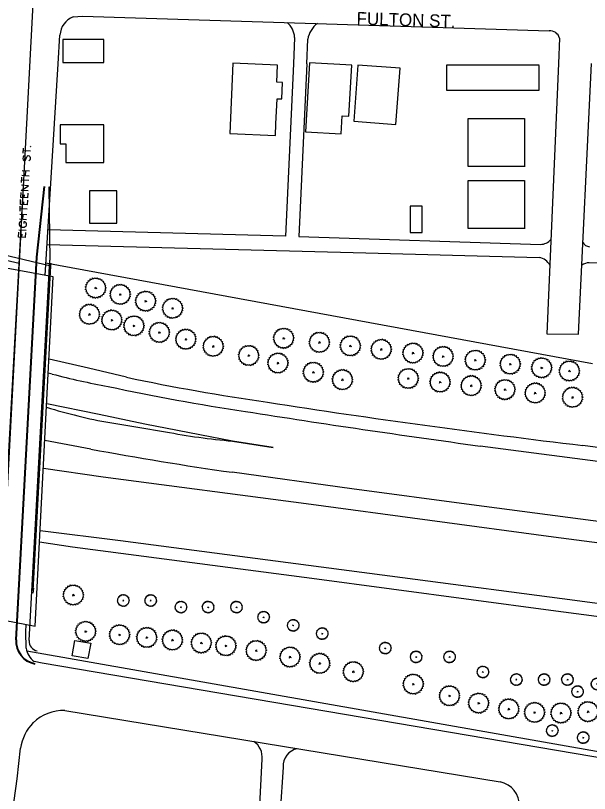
# Model space of a CAD drawing. Extents: x -9648 to 41057, y -12373 to 40276.
# Drawn here: x 11005 to 11458, y -5031 to -4417 of the extents above; entities that cross this region are included whole.
import ezdxf

# ---------------------------------------------------------------- set-up
doc = ezdxf.new("R2010")
doc.units = 0
for name, color, linetype in [('Default', 7, 'Continuous'), ('GE_P_CL_50', 7, 'Continuous'), ('PM_X_Channelizing_Line', 7, 'Continuous'), ('PM_X_Dotted_Line', 7, 'Continuous'), ('PM_X_Stop_Line', 7, 'Continuous'), ('PV_P_Shoulder', 7, 'Continuous'), ('SC_Scratch1', 7, 'Continuous'), ('SH_Data', 7, 'Continuous'), ('TX_P_100', 7, 'Continuous')]:
    doc.layers.add(name, color=color, linetype=linetype)

# ---------------------------------------------------------------- blocks, each defined once
blk = doc.blocks.new('15_PIN')
at = {"layer": 'Default'}
for p, q in [((-2.8, 0), (2.8, 0)), ((0, 2.8), (0, -2.8))]:
    blk.add_line(p, q, dxfattribs=at)
for centre, start, end in [((-16.7, 19.8), 235.99, 24.01), ((-11.6, 23.2), 222.6567, 10.6766), ((-6, 25.2), 209.3234, 357.3433), ((0, 25.9), 195.99, 344.01), ((6, 25.2), 182.6567, 330.6766), ((11.6, 23.2), 169.3234, 317.3433), ((16.7, 19.8), 155.99, 304.01), ((-25.5, 4.5), 275.99, 64.01), ((-25.9, -1.5), 289.3234, 77.3433), ((-23.8, 10.3), 262.6567, 50.6766), ((-20.8, 15.5), 249.3234, 37.3433), ((20.8, 15.5), 142.6567, 290.6766), ((23.8, 10.3), 129.3234, 277.3433), ((25.5, 4.5), 115.99, 264.01), ((25.9, -1.5), 102.6567, 250.6766), ((-24.8, -7.4), 302.6567, 90.6766), ((-22.4, -13), 315.99, 104.01), ((-18.8, -17.8), 329.3234, 117.3433), ((-14.2, -21.6), 342.6567, 130.6766), ((14.2, -21.6), 49.3234, 197.3433), ((18.8, -17.8), 62.6567, 210.6767), ((22.4, -13), 75.99, 224.01), ((24.8, -7.4), 89.3234, 237.3433), ((-8.9, -24.3), 355.99, 144.01), ((-3, -25.7), 9.3234, 157.3433), ((3, -25.7), 22.6567, 170.6766), ((8.9, -24.3), 35.99, 184.01)]:
    blk.add_arc(centre, 3.05, start, end, dxfattribs=at)

msp = doc.modelspace()

# ---------------------------------------------------------------- linework, layer by layer
at = {"layer": 'GE_P_CL_50'}
for p, q in [((11022.27, -4607.98), (11028.39, -4552.14)), ((11031.46, -4552.28), (11032.16, -4610.35)), ((11005.84, -4909.67), (11022.27, -4607.98)), ((11015.82, -4910.22), (11032.16, -4610.35))]:
    msp.add_line(p, q, dxfattribs=at)
for radius in [18, 8]:
    msp.add_arc((11023.81, -4910.65), radius, 176.88179, 259.41889, dxfattribs=at)
at = {"layer": 'PM_X_Channelizing_Line'}
for p, q in [((11021.77, -4607.98), (11027.88, -4552.16)), ((11005.34, -4909.65), (11021.78, -4607.9))]:
    msp.add_line(p, q, dxfattribs=at)
msp.add_arc((11023.81, -4910.65), 18.5, 176.88179, 259.41889, dxfattribs=at)
at = {"layer": 'PM_X_Dotted_Line'}
msp.add_line((10993.12, -4885.67), (11011.35, -4551.18), dxfattribs=at)
at = {"layer": 'PM_X_Stop_Line'}
for p in [(10981.18, -4602.61), (11018.97, -4870.86)]:
    msp.add_line(p, (11032.93, -4614.63), dxfattribs=at)
msp.add_arc((9361.23, -8468.95), 3904.03, 82.5, 82.5, dxfattribs=at)
at = {"layer": 'PV_P_Shoulder'}
msp.add_line((10980.21, -4606.15), (11008, -4612.61), dxfattribs=at)
at = {"layer": 'SC_Scratch1'}
for p, q in [((10990.47, -4947.21), (11071.82, -3407.25)), ((10949.85, -5716.14), (11031.09, -4178.28)), ((11011.47, -4521.79), (11011.47, -4521.79)), ((11016.7, -4520.6), (11016.7, -4520.6)), ((11016.91, -4520.86), (11016.91, -4520.86)), ((11016.93, -4520.37), (11016.93, -4520.37)), ((11017.14, -4520.63), (11017.14, -4520.63)), ((11011.25, -4525.85), (11011.25, -4525.85)), ((11011.36, -4523.76), (11011.36, -4523.76)), ((11011.93, -4527.62), (11011.93, -4527.62)), ((11014.6, -4528.01), (11014.6, -4528.01)), ((11015.18, -4527.8), (11015.18, -4527.8)), ((11015.96, -4527.84), (11015.96, -4527.84)), ((11016.95, -4524.07), (11016.95, -4524.07)), ((11011, -4530.16), (11011, -4530.16)), ((11011.07, -4529.05), (11011.07, -4529.05)), ((11011.18, -4531.03), (11011.18, -4531.03)), ((11011.34, -4528.2), (11011.34, -4528.2)), ((11011.71, -4531.68), (11011.71, -4531.68)), ((11012.27, -4531.71), (11012.27, -4531.71)), ((11012.84, -4531.49), (11012.84, -4531.49)), ((11013.08, -4531.26), (11013.08, -4531.26)), ((11013.34, -4530.66), (11013.34, -4530.66)), ((11013.99, -4528.84), (11013.99, -4528.84)), ((11014.25, -4528.37), (11014.25, -4528.37)), ((11015.73, -4531.9), (11015.73, -4531.9)), ((11016.33, -4531.32), (11016.33, -4531.32)), ((11016.48, -4528.49), (11016.48, -4528.49)), ((11016.6, -4530.47), (11016.6, -4530.47)), ((11016.66, -4529.36), (11016.66, -4529.36)), ((11010.49, -4539.51), (11010.49, -4539.51)), ((11013.17, -4539.66), (11013.17, -4539.66)), ((11016.08, -4539.82), (11016.08, -4539.82)), ((11010.2, -4544.8), (11010.2, -4544.8)), ((11010.26, -4543.57), (11010.26, -4543.57)), ((11012.95, -4543.72), (11012.95, -4543.72)), ((11015.85, -4543.88), (11015.85, -4543.88)), ((11009.84, -4551.19), (11009.84, -4551.19)), ((11009.97, -4548.86), (11009.97, -4548.86)), ((11010.08, -4546.77), (11010.08, -4546.77)), ((11015.43, -4551.51), (11015.43, -4551.51)), ((11015.68, -4547.07), (11015.68, -4547.07)), ((11009.52, -4556.98), (11009.52, -4556.98)), ((11009.61, -4555.25), (11009.61, -4555.25)), ((11012.12, -4558.6), (11012.12, -4558.6)), ((11015.11, -4557.28), (11015.11, -4557.28)), ((11015.2, -4555.56), (11015.2, -4555.56)), ((11009.21, -4562.51), (11009.21, -4562.51)), ((11009.31, -4560.79), (11009.31, -4560.79)), ((11011.81, -4564.14), (11011.81, -4564.14)), ((11011.99, -4560.94), (11011.99, -4560.94)), ((11014.8, -4562.82), (11014.8, -4562.82)), ((11014.9, -4561.1), (11014.9, -4561.1)), ((11014.9, -4561.1), (11014.9, -4561.1)), ((11008.82, -4569.52), (11008.82, -4569.52)), ((11008.93, -4567.55), (11008.93, -4567.55)), ((11009, -4566.33), (11009, -4566.33)), ((11011.68, -4566.47), (11011.68, -4566.47)), ((11014.41, -4569.83), (11014.41, -4569.83)), ((11014.59, -4566.63), (11014.59, -4566.63)), ((11014.59, -4566.63), (11014.59, -4566.63)), ((11008.58, -4573.95), (11008.58, -4573.95)), ((11008.71, -4571.61), (11008.71, -4571.61)), ((11011.26, -4574.1), (11011.26, -4574.1)), ((11014.17, -4574.26), (11014.17, -4574.26)), ((11008.1, -4582.44), (11008.1, -4582.44)), ((11008.17, -4581.21), (11008.17, -4581.21)), ((11008.3, -4582.94), (11008.3, -4582.94)), ((11008.35, -4578.01), (11008.35, -4578.01)), ((11008.43, -4580.61), (11008.43, -4580.61)), ((11009.02, -4580.14), (11009.02, -4580.14)), ((11009.59, -4579.81), (11009.59, -4579.81)), ((11011.03, -4578.16), (11011.03, -4578.16)), ((11011.64, -4581.4), (11011.64, -4581.4)), ((11011.72, -4579.93), (11011.72, -4579.93)), ((11012.5, -4579.97), (11012.5, -4579.97)), ((11013.04, -4580.37), (11013.04, -4580.37)), ((11013.45, -4583.23), (11013.45, -4583.23)), ((11013.58, -4580.89), (11013.58, -4580.89)), ((11013.7, -4582.75), (11013.7, -4582.75)), ((11013.76, -4581.52), (11013.76, -4581.52)), ((11013.94, -4578.32), (11013.94, -4578.32)), ((11007.78, -4588.22), (11007.78, -4588.22)), ((11007.88, -4586.5), (11007.88, -4586.5)), ((11008.82, -4583.59), (11008.82, -4583.59)), ((11009.36, -4583.99), (11009.36, -4583.99)), ((11010.13, -4584.28), (11010.13, -4584.28)), ((11011.47, -4584.35), (11011.47, -4584.35)), ((11012.27, -4584.15), (11012.27, -4584.15)), ((11012.85, -4583.81), (11012.85, -4583.81)), ((11013.37, -4588.53), (11013.37, -4588.53)), ((11013.47, -4586.81), (11013.47, -4586.81)), ((11007.57, -4592.03), (11007.57, -4592.03)), ((11010.25, -4592.18), (11010.25, -4592.18)), ((11010.38, -4589.85), (11010.38, -4589.85)), ((11013.16, -4592.34), (11013.16, -4592.34))]:
    msp.add_line(p, q, dxfattribs=at)
for points in [[(11011.25, -4525.85), (11011.47, -4521.79)], [(11011.25, -4525.85), (11011.47, -4521.79)], [(11016.7, -4520.6), (11016.91, -4520.86), (11017.14, -4520.63), (11016.93, -4520.37)], [(11016.7, -4520.6), (11016.91, -4520.86), (11017.14, -4520.63), (11016.93, -4520.37)], [(11011.93, -4527.62), (11011.34, -4528.2), (11011.07, -4529.05), (11011, -4530.16), (11011.18, -4531.03), (11011.71, -4531.68), (11012.27, -4531.71), (11012.84, -4531.49), (11013.08, -4531.26), (11013.34, -4530.66), (11013.99, -4528.84), (11014.25, -4528.37), (11014.6, -4528.01), (11015.18, -4527.8), (11015.96, -4527.84), (11016.48, -4528.49), (11016.66, -4529.36), (11016.6, -4530.47), (11016.33, -4531.32), (11015.73, -4531.9)], [(11011.93, -4527.62), (11011.34, -4528.2), (11011.07, -4529.05), (11011, -4530.16), (11011.18, -4531.03), (11011.71, -4531.68), (11012.27, -4531.71), (11012.84, -4531.49), (11013.08, -4531.26), (11013.34, -4530.66), (11013.99, -4528.84), (11014.25, -4528.37), (11014.6, -4528.01), (11015.18, -4527.8), (11015.96, -4527.84), (11016.48, -4528.49), (11016.66, -4529.36), (11016.6, -4530.47), (11016.33, -4531.32), (11015.73, -4531.9)], [(11011.36, -4523.76), (11016.95, -4524.07)], [(11011.36, -4523.76), (11016.95, -4524.07)], [(11010.49, -4539.51), (11016.08, -4539.82)], [(11010.49, -4539.51), (11016.08, -4539.82)], [(11012.95, -4543.72), (11013.17, -4539.66)], [(11012.95, -4543.72), (11013.17, -4539.66)], [(11009.97, -4548.86), (11010.2, -4544.8)], [(11009.97, -4548.86), (11010.2, -4544.8)], [(11015.85, -4543.88), (11010.26, -4543.57)], [(11015.85, -4543.88), (11010.26, -4543.57)], [(11015.2, -4555.56), (11009.61, -4555.25), (11015.43, -4551.51), (11009.84, -4551.19)], [(11015.2, -4555.56), (11009.61, -4555.25), (11015.43, -4551.51), (11009.84, -4551.19)], [(11010.08, -4546.77), (11015.68, -4547.07)], [(11010.08, -4546.77), (11015.68, -4547.07)], [(11014.9, -4561.1), (11009.31, -4560.79), (11009.52, -4556.98)], [(11014.9, -4561.1), (11009.31, -4560.79), (11009.52, -4556.98)], [(11011.99, -4560.94), (11012.12, -4558.6)], [(11011.99, -4560.94), (11012.12, -4558.6)], [(11014.9, -4561.1), (11015.11, -4557.28)], [(11014.9, -4561.1), (11015.11, -4557.28)], [(11014.59, -4566.63), (11009, -4566.33), (11009.21, -4562.51)], [(11014.59, -4566.63), (11009, -4566.33), (11009.21, -4562.51)], [(11011.68, -4566.47), (11011.81, -4564.14)], [(11011.68, -4566.47), (11011.81, -4564.14)], [(11014.59, -4566.63), (11014.8, -4562.82)], [(11014.59, -4566.63), (11014.8, -4562.82)], [(11008.71, -4571.61), (11008.93, -4567.55)], [(11008.71, -4571.61), (11008.93, -4567.55)], [(11008.82, -4569.52), (11014.41, -4569.83)], [(11008.82, -4569.52), (11014.41, -4569.83)], [(11008.58, -4573.95), (11014.17, -4574.26)], [(11008.58, -4573.95), (11014.17, -4574.26)], [(11011.03, -4578.16), (11011.26, -4574.1)], [(11011.03, -4578.16), (11011.26, -4574.1)], [(11009.59, -4579.81), (11009.02, -4580.14), (11008.43, -4580.61), (11008.17, -4581.21), (11008.1, -4582.44), (11008.3, -4582.94), (11008.82, -4583.59), (11009.36, -4583.99), (11010.13, -4584.28), (11011.47, -4584.35), (11012.27, -4584.15), (11012.85, -4583.81), (11013.45, -4583.23), (11013.7, -4582.75), (11013.76, -4581.52), (11013.58, -4580.89), (11013.04, -4580.37), (11012.5, -4579.97), (11011.72, -4579.93), (11011.64, -4581.4)], [(11009.59, -4579.81), (11009.02, -4580.14), (11008.43, -4580.61), (11008.17, -4581.21), (11008.1, -4582.44), (11008.3, -4582.94), (11008.82, -4583.59), (11009.36, -4583.99), (11010.13, -4584.28), (11011.47, -4584.35), (11012.27, -4584.15), (11012.85, -4583.81), (11013.45, -4583.23), (11013.7, -4582.75), (11013.76, -4581.52), (11013.58, -4580.89), (11013.04, -4580.37), (11012.5, -4579.97), (11011.72, -4579.93), (11011.64, -4581.4)], [(11013.94, -4578.32), (11008.35, -4578.01)], [(11013.94, -4578.32), (11008.35, -4578.01)], [(11013.16, -4592.34), (11007.57, -4592.03), (11007.78, -4588.22)], [(11013.16, -4592.34), (11007.57, -4592.03), (11007.78, -4588.22)], [(11013.47, -4586.81), (11007.88, -4586.5)], [(11013.47, -4586.81), (11007.88, -4586.5)], [(11013.16, -4592.34), (11013.37, -4588.53)], [(11013.16, -4592.34), (11013.37, -4588.53)], [(11010.25, -4592.18), (11010.38, -4589.85)], [(11010.25, -4592.18), (11010.38, -4589.85)]]:
    msp.add_lwpolyline(points, dxfattribs=at)
at = {"layer": 'SH_Data'}
for p, q in [((11038.85, -4455.45), (11040.24, -4432.65)), ((11225.24, -4434.54), (11224.45, -4455.35)), ((11234.85, -4455.34), (11235.64, -4435.94)), ((11434.24, -4435.03), (11433.45, -4455.23)), ((11042.51, -4436.22), (11042.51, -4454.25)), ((11074.85, -4436.22), (11042.51, -4436.22)), ((11074.85, -4454.25), (11074.85, -4436.22)), ((11042.51, -4454.25), (11074.85, -4454.25)), ((11028.56, -4622.25), (11038.85, -4455.45)), ((11176.64, -4454.73), (11174.1, -4510.31)), ((11211.75, -4456.33), (11176.64, -4454.73)), ((11211.13, -4469.9), (11211.75, -4456.33)), ((11236.89, -4454.61), (11233.85, -4509.08)), ((11270.37, -4456.48), (11236.89, -4454.61)), ((11268.13, -4496.6), (11270.37, -4456.48)), ((11275.13, -4456.32), (11271.87, -4500.68)), ((11308.42, -4458.77), (11275.13, -4456.32)), ((11305.17, -4503.12), (11308.42, -4458.77)), ((11345.32, -4476.36), (11345.32, -4456.07)), ((11345.32, -4456.07), (11418.1, -4456.07)), ((11417.8, -4456.67), (11417.8, -4476.36)), ((11215.65, -4470.1), (11211.13, -4469.9)), ((11215.06, -4483.04), (11215.65, -4470.1)), ((11417.8, -4476.36), (11345.32, -4476.36)), ((11210.54, -4502.73), (11211.44, -4482.88)), ((11211.44, -4482.88), (11215.06, -4483.04)), ((11261.96, -4510.64), (11262.76, -4496.3)), ((11262.76, -4496.3), (11268.13, -4496.6)), ((11040.28, -4503.41), (11040.28, -4518.46)), ((11074.85, -4503.41), (11040.28, -4503.41)), ((11074.85, -4533.28), (11074.85, -4503.41)), ((11210.12, -4511.96), (11210.54, -4502.73)), ((11271.87, -4500.68), (11305.17, -4503.12)), ((11362.02, -4536.33), (11362.02, -4498.44)), ((11362.02, -4498.44), (11406.47, -4498.44)), ((11406.47, -4498.44), (11406.47, -4536.63)), ((11233.85, -4509.08), (11261.96, -4510.64)), ((11174.1, -4510.31), (11210.12, -4511.96)), ((11040.28, -4518.46), (11044.97, -4518.46)), ((11044.97, -4518.46), (11044.97, -4533.28)), ((11044.97, -4533.28), (11074.85, -4533.28)), ((11406.17, -4536.33), (11362.02, -4536.33)), ((11362.02, -4585.25), (11362.02, -4547.36)), ((11362.02, -4547.36), (11406.47, -4547.36)), ((11406.47, -4547.36), (11406.47, -4585.55)), ((11063.49, -4555.51), (11063.49, -4581.19)), ((11084.97, -4555.51), (11063.49, -4555.51)), ((11084.97, -4581.19), (11084.97, -4555.51)), ((11316.31, -4567.61), (11316.31, -4588.36)), ((11325.94, -4567.61), (11316.31, -4567.61)), ((11325.94, -4588.36), (11325.94, -4567.61)), ((11063.49, -4581.19), (11084.97, -4581.19)), ((11316.31, -4588.36), (11325.94, -4588.36)), ((11406.17, -4585.25), (11362.02, -4585.25)), ((11029.18, -4612.23), (11460.16, -4691.77)), ((11750.35, -4621.85), (11457.54, -4612.41)), ((11034.19, -4700.05), (11031.03, -4699.32)), ((11064.43, -4759.23), (11028.28, -4752.38)), ((11014, -4918.4), (11514.42, -5006.69)), ((11044.14, -4965.45), (11387.38, -5021.85)), ((11181.96, -5352.77), (11199.57, -5003.96)), ((11216.16, -5010.15), (11194.36, -5359.76))]:
    msp.add_line(p, q, dxfattribs=at)
for points in [[(11050.62, -4418.44), (11058.03, -4417.84), (11426.03, -4429.23)], [(11224.46, -4455.34), (11218.14, -4591.35), (11030.78, -4586.22)], [(11234.85, -4455.34), (11228.53, -4591.54), (11419.14, -4597.83)], [(11433.46, -4455.23), (11424.18, -4668.43), (11449.18, -4668.62), (11459.46, -4455.21)], [(11030.07, -4597.84), (11281.34, -4604.51), (11418.14, -4608.23)], [(11092.6, -4702.62), (11062.71, -4695.52), (11031.59, -4688.38)], [(11176.22, -4752.97), (11208.23, -4757.95), (11176.22, -4752.97), (11107.01, -4739.61), (11071.01, -4732.03), (11029.77, -4723.58)], [(11079.62, -4738.42), (11101.51, -4742.02), (11123.42, -4745.6)], [(11803.26, -4813.82), (11698.37, -4799.67), (11593.44, -4785.94), (11482.52, -4771.41), (11371.63, -4756.86)], [(11719.44, -4791.47), (11585.89, -4774.29), (11452.43, -4756.42)], [(12047.7, -4910.08), (11942.71, -4896.14), (11817.04, -4879.4), (11691.29, -4863.48), (11560.39, -4845.94), (11429.47, -4828.63), (11331.84, -4815.68), (11234.25, -4802.54), (11074.24, -4781.43), (11027.15, -4774.45)], [(12047.69, -4893.08), (11972.7, -4883.12), (11872.75, -4870.19), (11772.87, -4856.84), (11694.87, -4846.65), (11616.86, -4836.52), (11490.76, -4819.79), (11364.65, -4803.27), (11270.3, -4790.73), (11176.03, -4777.57)], [(12047.73, -4957.68), (11819.52, -4927.41), (11700.8, -4912.08), (11582.1, -4896.74), (11446.2, -4878.61), (11310.28, -4860.69), (11087.86, -4831.62), (11024.6, -4823.65)], [(11735.11, -4927.46), (11581.23, -4906.8), (11427.3, -4886.63), (11238.71, -4861.33), (11050.06, -4836.64), (11024.14, -4832.67)], [(11013.52, -4916.26), (11013.21, -4903.37), (11013.51, -4897.68)], [(12047.81, -5101.68), (12020.01, -5096.9), (11026.11, -4928.25), (11019.91, -4926.86)], [(10984.34, -5335.28), (11000.79, -5061.07), (11006.38, -5019.27), (11009.15, -4995.26)]]:
    msp.add_lwpolyline(points, dxfattribs=at)
for points in [[(10966, -4888.49), (11020.71, -4899.06), (11034.94, -4623.45), (10980.54, -4613.28)], [(11049.91, -4922.24), (11051.9, -4910.24), (11064.51, -4912.43), (11062.32, -4924.43)]]:
    msp.add_lwpolyline(points, close=True, dxfattribs=at)
for centre, radius, start, end in [((11056.1, -4433.35), 15.88, 110.15518, 177.47118), ((11208.71, -4435.53), 16.56, 3.41018, 50.09618), ((11254.67, -4439.1), 19.29, 126.39818, 170.56218), ((11426.35, -4437.49), 8.26, 17.33318, 92.18618), ((11418.83, -4586.42), 11.41, 271.52918, 318.74918), ((11457.98, -4593.83), 5.79, 203.38118, 267.49718), ((11416.37, -4619.53), 11.44, 27.22318, 81.06718), ((11456.97, -4620.78), 8.39, 86.04618, 128.05818), ((11170.24, -4191.54), 526.4, 255.02218, 259.93018), ((11456.79, -2971.29), 1769.22, 258.12018, 261.78518), ((11439.62, -3032.4), 1715.92, 257.84118, 261.52118), ((12289.64, 2273.07), 7079.16, 261.178183, 263.208183), ((11154.92, -4317.75), 427.36, 252.95118, 259.85018), ((12539.25, 3798.1), 8634.27, 260.987183, 262.228183), ((11224.03, -4217.6), 537.5, 259.21118, 264.89718), ((11532.56, -2258.99), 2543.69, 259.39518, 261.94318), ((11029.68, -4913.73), 16.36, 188.89118, 233.33718), ((11043.11, -5000.09), 34.66, 88.31518, 133.76318), ((11044.23, -5000.03), 35.4, 135.12918, 172.25918), ((11184.84, -5002.25), 14.82, 353.38918, 56.29218), ((11229.99, -5009.2), 13.86, 100.54518, 183.92818), ((11383.46, -5040.57), 19.13, 359.19018, 78.19418)]:
    msp.add_arc(centre, radius, start, end, dxfattribs=at)
at = {"layer": 'TX_P_100'}
for p, q in [((11032.47, -4616.58), (11033.38, -4612.69)), ((11019.23, -4868.87), (11018.71, -4872.84))]:
    msp.add_line(p, q, dxfattribs=at)

# ---------------------------------------------------------------- block references
at = {"layer": 'SH_Data'}
for p, xscale, yscale, rotation in [((11068.38, -4632.16), 0.32808397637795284, 0.32808397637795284, 64.61472397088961), ((11087.72, -4637.27), 0.32808397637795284, 0.32808397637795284, 64.61472397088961), ((11107.76, -4642.57), 0.32808397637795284, 0.32808397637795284, 64.61472397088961), ((11129.02, -4648.19), 0.32808397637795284, 0.32808397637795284, 64.61472397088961), ((11063.49, -4652.97), 0.32808397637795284, 0.32808397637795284, 64.61472397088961), ((11081.12, -4657.52), 0.32808397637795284, 0.32808397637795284, 64.61472397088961), ((11098.54, -4662.03), 0.32808397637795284, 0.32808397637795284, 64.61472397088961), ((11118.61, -4667.22), 0.32808397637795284, 0.32808397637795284, 64.61472397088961), ((11139.48, -4672.61), 0.32808397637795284, 0.32808397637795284, 64.61472397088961), ((11216.58, -4671.8), 0.32808397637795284, 0.32808397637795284, 64.61472397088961), ((11161.07, -4678.2), 0.32808397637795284, 0.32808397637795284, 64.61472397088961), ((11244.8, -4675.04), 0.32808397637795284, 0.32808397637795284, 64.61472397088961), ((11269.22, -4677.83), 0.32808397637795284, 0.32808397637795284, 64.61472397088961), ((11189.08, -4685.44), 0.32808397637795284, 0.32808397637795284, 64.61472397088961), ((11293.54, -4680.62), 0.32808397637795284, 0.32808397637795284, 64.61472397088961), ((11318.57, -4683.49), 0.32808397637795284, 0.32808397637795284, 64.61472397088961), ((11342.36, -4686.22), 0.32808397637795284, 0.32808397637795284, 64.61472397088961), ((11212.1, -4691.39), 0.32808397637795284, 0.32808397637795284, 64.61472397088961), ((11367.69, -4689.12), 0.32808397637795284, 0.32808397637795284, 64.61472397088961), ((11395.29, -4692.28), 0.32808397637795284, 0.32808397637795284, 64.61472397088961), ((11240.03, -4698.61), 0.32808397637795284, 0.32808397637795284, 64.61472397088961), ((11420.04, -4695.12), 0.32808397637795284, 0.32808397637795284, 64.61472397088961), ((11441.93, -4697.63), 0.32808397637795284, 0.32808397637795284, 64.61472397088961), ((11262.95, -4704.54), 0.32808397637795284, 0.32808397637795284, 64.61472397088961), ((11314.85, -4703.57), 0.32808397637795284, 0.32808397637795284, 64.61472397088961), ((11339.98, -4706.45), 0.32808397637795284, 0.32808397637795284, 64.61472397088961), ((11364.48, -4709.26), 0.32808397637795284, 0.32808397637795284, 64.61472397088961), ((11391.14, -4712.31), 0.32808397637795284, 0.32808397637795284, 64.61472397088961), ((11414.93, -4715.04), 0.32808397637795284, 0.32808397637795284, 64.61472397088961), ((11444.39, -4718.42), 0.32808397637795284, 0.32808397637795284, 64.61472397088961), ((11050.78, -4874.33), 0.32808397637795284, 0.32808397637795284, 64.61472397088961), ((11090.18, -4878.69), 0.19138193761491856, 0.19138193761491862, 64.6147239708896), ((11111.76, -4878.69), 0.19138193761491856, 0.19138193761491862, 64.6147239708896), ((11135.64, -4883.89), 0.19138193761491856, 0.19138193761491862, 64.6147239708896), ((11157.02, -4883.89), 0.19138193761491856, 0.19138193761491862, 64.6147239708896), ((11179.39, -4883.89), 0.19138193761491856, 0.19138193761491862, 64.6147239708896), ((11200.77, -4891.85), 0.19138193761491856, 0.19138193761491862, 64.6147239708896), ((11060.49, -4903.07), 0.32808397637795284, 0.32808397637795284, 64.61472397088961), ((11087.22, -4905.73), 0.32808397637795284, 0.32808397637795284, 64.61472397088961), ((11224.13, -4898.31), 0.19138193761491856, 0.19138193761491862, 64.6147239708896), ((11108.68, -4907.87), 0.32808397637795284, 0.32808397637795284, 64.61472397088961), ((11128.9, -4909.88), 0.32808397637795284, 0.32808397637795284, 64.61472397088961), ((11151.69, -4912.15), 0.32808397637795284, 0.32808397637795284, 64.61472397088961), ((11247, -4904.78), 0.19138193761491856, 0.19138193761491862, 64.6147239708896), ((11171.07, -4914.43), 0.32808397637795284, 0.32808397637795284, 64.61472397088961), ((11194.95, -4918.17), 0.32808397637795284, 0.32808397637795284, 64.61472397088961), ((11221.61, -4923.26), 0.32808397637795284, 0.32808397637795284, 64.61472397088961), ((11296.71, -4916.22), 0.19138193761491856, 0.19138193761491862, 64.6147239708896), ((11245.08, -4928.29), 0.32808397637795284, 0.32808397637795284, 64.61472397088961), ((11321.06, -4923.18), 0.19138193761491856, 0.19138193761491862, 64.6147239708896), ((11347.41, -4923.18), 0.19138193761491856, 0.19138193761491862, 64.6147239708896), ((11271.54, -4934.82), 0.32808397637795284, 0.32808397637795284, 64.61472397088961), ((11373.76, -4935.11), 0.19138193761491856, 0.19138193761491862, 64.6147239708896), ((11318.82, -4944.63), 0.32808397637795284, 0.32808397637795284, 64.61472397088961), ((11400.1, -4941.08), 0.19138193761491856, 0.19138193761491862, 64.6147239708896), ((11421.98, -4941.08), 0.19138193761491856, 0.19138193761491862, 64.6147239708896), ((11440.37, -4941.08), 0.19138193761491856, 0.19138193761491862, 64.6147239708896), ((11463.73, -4944.56), 0.19138193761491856, 0.19138193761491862, 64.6147239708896), ((11347.39, -4953.88), 0.32808397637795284, 0.32808397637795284, 64.61472397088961), ((11448.32, -4950.53), 0.19138193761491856, 0.19138193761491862, 64.6147239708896), ((11370.35, -4959.63), 0.32808397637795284, 0.32808397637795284, 64.61472397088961), ((11394.14, -4964.24), 0.32808397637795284, 0.32808397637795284, 64.61472397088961), ((11414.45, -4966.98), 0.32808397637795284, 0.32808397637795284, 64.61472397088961), ((11435.29, -4967.41), 0.32808397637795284, 0.32808397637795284, 64.61472397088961), ((11456.64, -4966.34), 0.32808397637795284, 0.32808397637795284, 64.61472397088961), ((11428.44, -4981.36), 0.19138193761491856, 0.19138193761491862, 64.6147239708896), ((11452.8, -4986.83), 0.19138193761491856, 0.19138193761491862, 64.6147239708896)]:
    msp.add_blockref('15_PIN', p, dxfattribs=dict(at, xscale=xscale, yscale=yscale, rotation=rotation))

# ---------------------------------------------------------------- texts
at = {"layer": 'SC_Scratch1'}
msp.add_text('FULTON ST.', height=10, rotation=358.22712, dxfattribs=at).set_placement((11273.99, -4424.45))

doc.saveas('drawing.dxf')
